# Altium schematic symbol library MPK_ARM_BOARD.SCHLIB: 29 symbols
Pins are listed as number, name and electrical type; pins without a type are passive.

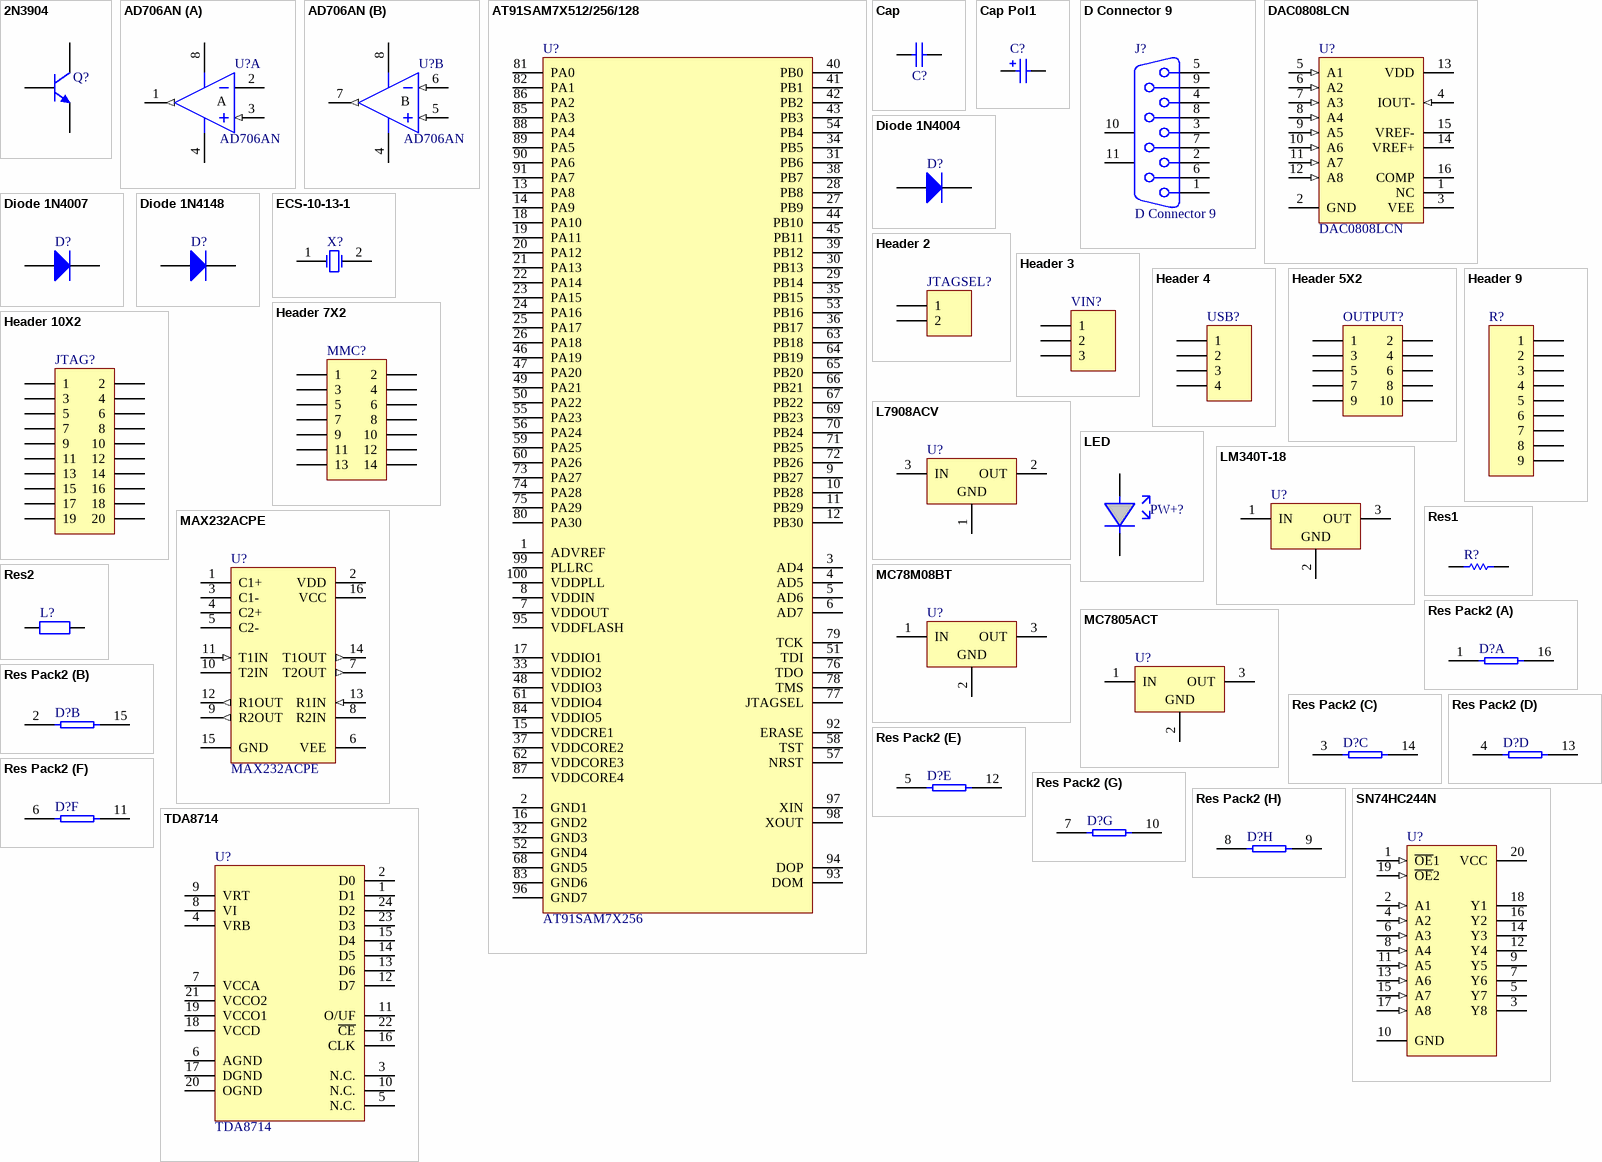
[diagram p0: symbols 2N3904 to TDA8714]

## 2N3904
designator Q?  (value not drawn)
NPN General Purpose Amplifier; Revision 1: 11-Jul-2000: SIM Model Added.; Revision 2: 17-Jul-2002: Re-released for DXP Platform.; Revision 3: 15-Jan-2003: PCB Footprint 'BCY-W3/D4.7' replaced; Code - JEDEC: TO-92A
footprint BCY-W3/E4 (TO, Flat Index; 3 In-Line, Axial Leads; Body Dia. 4.7mm)
simulation model 2N3904 (NPN)
signal-integrity model 2N3904
pins: 1 E, 2 B, 3 C

## AD706AN
designator U?
Dual Picoampere Input Current Bipolar Operational Amplifier; Revision 1: 10-Jul-2000: SIM Model Added.; Revision 2: 17-Jul-2002: Re-released for DXP Platform.; Code - JEDEC: MO-001-AN
footprint N-8_A (DIP; 8 Leads; Row Spacing 7.62 mm; Pitch 2.54 mm)
simulation model AD706A (SUBCKT)
pins on every part: 4 V- (power), 8 V+ (power)
part A pins: 1 OUT (out), 2 IN-, 3 IN+ (in)
part B pins: 5 IN+ (in), 6 IN- (in), 7 OUT (out)

## AT91SAM7X512/256/128
designator U?, comment AT91SAM7X256
Atmel ARM Core 32 Microcontroller
footprint LQFP100 (QFP; 100 Leads; Body 14 x 14 mm; Pitch 0.5 mm)
pins: 1 ADVREF, 2 GND1, 3 AD4, 4 AD5, 5 AD6, 6 AD7, 7 VDDOUT, 8 VDDIN, 9 PB27, 10 PB28, 11 PB29, 12 PB30, 13 PA8, 14 PA9, 15 VDDCRE1, 16 GND2, 17 VDDIO1, 18 PA10, 19 PA11, 20 PA12, 21 PA13, 22 PA14, 23 PA15, 24 PA16, 25 PA17, 26 PA18, 27 PB9, 28 PB8, 29 PB14, 30 PB13, 31 PB6, 32 GND3, 33 VDDIO2, 34 PB5, 35 PB15, 36 PB17, 37 VDDCORE2, 38 PB7, 39 PB12, 40 PB0, 41 PB1, 42 PB2, 43 PB3, 44 PB10, 45 PB11, 46 PA19, 47 PA20, 48 VDDIO3, 49 PA21, 50 PA22, 51 TDI, 52 GND4, 53 PB16, 54 PB4, 55 PA23, 56 PA24, 57 NRST, 58 TST, 59 PA25, 60 PA26, 61 VDDIO4, 62 VDDCORE3, 63 PB18, 64 PB19, 65 PB20, 66 PB21, 67 PB22, 68 GND5, 69 PB23, 70 PB24, 71 PB25, 72 PB26, 73 PA27, 74 PA28, 75 PA29, 76 TDO, 77 JTAGSEL, 78 TMS, 79 TCK, 80 PA30, 81 PA0, 82 PA1, 83 GND6, 84 VDDIO5, 85 PA3, 86 PA2, 87 VDDCORE4, 88 PA4, 89 PA5, 90 PA6, 91 PA7, 92 ERASE, 93 DOM, 94 DOP, 95 VDDFLASH, 96 GND7, 97 XIN, 98 XOUT, 99 PLLRC, 100 VDDPLL

## Cap
designator C?  (value not drawn)
Capacitor; Value: 100pF
footprint RAD-0.3
simulation model CAP (Capacitor)
signal-integrity model Cap
footprint CAPR5.08-7.8X3.2
footprint CAPR2.54-5.1X3.2
pins: 1, 2

## Cap Pol1
designator C?  (value not drawn)
Polarized Capacitor (Radial); Value: 100pF
footprint RB7.6-15 (Polarized Capacitor (Radial); 2 Leads)
simulation model CAP (Capacitor)
signal-integrity model Cap Pol
footprint CAPPR1.5-4X5
footprint CAPPR1.27-1.96X4.06
footprint CAPPR2-5X6.8
footprint CAPPR5-5X5
footprint CAPPR7.5-16X35
pins: 1, 2

## D Connector 9
designator J?
Receptacle Assembly, 9 Position, Right Angle; Package Information: Latest Revision: O; Positions: 9
footprint DSUB1.385-2H9 (Connector; D Subminiature; 9 Position; Right Angle; Pitch 1.385 mm)
signal-integrity model Connector
pins: 1, 2, 3, 4, 5, 6, 7, 8, 9, 10 MH1, 11 MH2

## DAC0808LCN
designator U?
8-Bit D/A Converter; Package Information: Latest Revision: 2000
footprint N16A (DIP; 16 Leads; Row Spacing 7.62 mm; Pitch 2.54 mm)
pins: 1 NC, 2 GND (power), 3 VEE (power), 4 IOUT- (in), 5 A1 (in), 6 A2 (in), 7 A3 (in), 8 A4 (in), 9 A5 (in), 10 A6 (in), 11 A7 (in), 12 A8 (in), 13 VDD (power), 14 VREF+, 15 VREF-, 16 COMP

## Diode 1N4004
designator D?  (value not drawn)
1 Amp General Purpose Rectifier; Revision 1: 11-Jul-2000: SIM Model Added.; Revision 2: 17-Jul-2002: Re-released for DXP Platform.; Package Information: Latest Revision: Aug-1999; Code - JEDEC: DO-204-AL
footprint DIO10.46-5.3x2.8 (Diode, Axial; Body 5.2 x 2.7 mm (LxDia. max), Lead Dia. 0.86 mm (max))
simulation model 1N4004 (DIODE)
signal-integrity model 1N4004
pins: 1 A, 2 K

## Diode 1N4007
designator D?  (value not drawn)
1 Amp General Purpose Rectifier; Revision 1: 11-Jul-2000: SIM Model Added.; Revision 2: 17-Jul-2002: Re-released for DXP Platform.; Package Information: Latest Revision: Aug-1999; Code - JEDEC: DO-204-AL
footprint DIO10.46-5.3x2.8 (Diode, Axial; Body 5.2 x 2.7 mm (LxDia. max), Lead Dia. 0.86 mm (max))
simulation model 1N4007 (DIODE)
signal-integrity model 1N4007
pins: 1 A, 2 K

## Diode 1N4148
designator D?  (value not drawn)
High Conductance Fast Diode; Revision 1: 11-Jul-2000: SIM Model Added.; Revision 2: 17-Jul-2002: Re-released for DXP Platform.; Code - JEDEC: DO-204-AH
footprint DIO7.1-3.9x1.9 (Diode, Axial; Body 3.8 x 1.9 mm (LxDia. max), Lead Dia. 0.53 mm (max))
simulation model 1N4148 (DIODE)
signal-integrity model 1N4148
pins: 1 A, 2 K

## ECS-10-13-1
designator X?  (value not drawn)
Crystal Oscillator
footprint HC-49U (Quartz Crystal, Thru-Hole; 2 Leads; Body 11.35 x 4.65 x 13.46 mm (LxWxH max))
simulation model XTAL (SUBCKT)
pins: 1 OSC1, 2 OSC2

## Header 2
designator JTAGSEL?  (value not drawn)
Header, 2-Pin
footprint HDR1X2 (Connector; Header; 2 Position)
signal-integrity model Connector
pins: 1, 2

## Header 3
designator VIN?  (value not drawn)
Header, 3-Pin
footprint HDR1X3 (Connector; Header; 3 Position)
signal-integrity model Connector
pins: 1, 2, 3

## Header 4
designator USB?  (value not drawn)
Header, 4-Pin
footprint HDR1X4 (Connector; Header; 4 Position)
signal-integrity model Connector
pins: 1, 2, 3, 4

## Header 5X2
designator OUTPUT?  (value not drawn)
Header, 5-Pin, Dual row
footprint HDR2X5 (Connector; Header; 5x2 Position)
signal-integrity model Connector
pins: 1, 2, 3, 4, 5, 6, 7, 8, 9, 10

## Header 7X2
designator MMC?  (value not drawn)
Header, 7-Pin, Dual row
footprint HDR2X7 (Connector; Header; 7x2 Position)
signal-integrity model Connector
pins: 1, 2, 3, 4, 5, 6, 7, 8, 9, 10, 11, 12, 13, 14

## Header 9
designator R?  (value not drawn)
Header, 9-Pin
footprint HDR1X9 (Connector; Header; 9 Position)
signal-integrity model Connector
pins: 1, 2, 3, 4, 5, 6, 7, 8, 9

## Header 10X2
designator JTAG?  (value not drawn)
Header, 10-Pin, Dual row
footprint HDR2X10 (Connector; Header; 10x2 Position)
signal-integrity model Connector
pins: 1, 2, 3, 4, 5, 6, 7, 8, 9, 10, 11, 12, 13, 14, 15, 16, 17, 18, 19, 20

## L7908ACV
designator U?  (value not drawn)
2% Negative Voltage Regulator; Note: Tab is connected to pin 3 (IN).
footprint TO220V (TO, Thru-Hole, Vertical, Heatsink Mounted; 3 In-Line Leads; Pitch 2.54 mm; Pin sequence 1, 3, 2)
pins: 1 GND (power), 2 OUT (power), 3 IN (power)

## LED
designator PW+?  (value not drawn)
footprint LED
pins: 1, 2

## LM340T-18
designator U?  (value not drawn)
3-Terminal Positive Fixed Voltage Regulator; Note: Heatsink surface connected to pin 2.; Code - JEDEC: TO-262-AA
footprint 221A-04 (TO, Thru-Hole, Vertical, Heatsink Mounted; 3 In-Line Leads; Pitch 2.54 mm)
pins: 1 IN (power), 2 GND (power), 3 OUT (power)

## MAX232ACPE
designator U?
+5V Powered, Multi-Channel RS-232 Driver/Receiver; Package Information: Latest Revision: 1997; Code - JEDEC: MS-001-BB
footprint PE16A (DIP; 16 Leads; Row Spacing 7.62 mm; Pitch 2.54 mm)
pins: 1 C1+, 2 VDD (power), 3 C1-, 4 C2+, 5 C2-, 6 VEE (power), 7 T2OUT (out), 8 R2IN, 9 R2OUT (out), 10 T2IN, 11 T1IN (in), 12 R1OUT (out), 13 R1IN (in), 14 T1OUT (out), 15 GND (power), 16 VCC (power)

## MC78M08BT
designator U?  (value not drawn)
3-Terminal Medium-Current Positive Fixed Voltage Regulator; Note: Pin 2 is electrically connected to TAB; Code - JEDEC: TO-262-AA
footprint 221A-04 (TO, Thru-Hole, Vertical, Heatsink Mounted; 3 In-Line Leads; Pitch 2.54 mm)
pins: 1 IN (power), 2 GND (power), 3 OUT (power)

## MC7805ACT
designator U?  (value not drawn)
3-Terminal Positive Fixed Voltage Regulator; Note: Pin 2 is electrically connected to TAB; Code - JEDEC: TO-262-AA
footprint 221A-04 (TO, Thru-Hole, Vertical, Heatsink Mounted; 3 In-Line Leads; Pitch 2.54 mm)
pins: 1 IN (power), 2 GND (power), 3 OUT (power)

## Res1
designator R?  (value not drawn)
Resistor; Value: 5.00K
footprint AXIAL-0.3 (Resistor; 2 Leads)
simulation model RESISTOR (Resistor)
signal-integrity model Res
pins: 1, 2
1 alternate drawing of the same symbol

## Res2
designator L?  (value not drawn)
Resistor; Value: 1K
footprint AXIAL-0.4 (Resistor; 2 Leads)
simulation model RESISTOR (Resistor)
signal-integrity model Res
pins: 1, 2
1 alternate drawing of the same symbol

## Res Pack2
designator D?  (value not drawn)
Resistor Array - Parts; Code - JEDEC: MO-001-AC; Value: 1K
footprint DIP-16 (DIP; 16 Leads; Row Spacing 7.62 mm; Pitch 2.54 mm)
simulation model RESISTOR (Resistor)
signal-integrity model Res Pack
part A pins: 1, 16
part B pins: 2, 15
part C pins: 3, 14
part D pins: 4, 13
part E pins: 5, 12
part F pins: 6, 11
part G pins: 7, 10
part H pins: 8, 9

## SN74HC244N
designator U?  (value not drawn)
Octal Buffer and Line Driver with 3-State Outputs; Package Information: Latest Revision: Oct-1995
footprint N020 (DIP; 20 Leads; Row Spacing 7.62 mm; Pitch 2.54 mm)
signal-integrity model SN74HC244N
pins: 1 ~{OE}1 (in), 2 A1 (in), 3 Y8 (hiz), 4 A2 (in), 5 Y7 (hiz), 6 A3 (in), 7 Y6 (hiz), 8 A4 (in), 9 Y5 (hiz), 10 GND (power), 11 A5 (in), 12 Y4 (hiz), 13 A6 (in), 14 Y3 (hiz), 15 A7 (in), 16 Y2 (hiz), 17 A8 (in), 18 Y1 (hiz), 19 ~{OE}2 (in), 20 VCC (power)

## TDA8714
designator U?
footprint SOP24
pins: 1 D1, 2 D0, 3 N.C., 4 VRB, 5 N.C., 6 AGND, 7 VCCA, 8 VI, 9 VRT, 10 N.C., 11 O/UF, 12 D7, 13 D6, 14 D5, 15 D4, 16 CLK, 17 DGND, 18 VCCD, 19 VCCO1, 20 OGND, 21 VCCO2, 22 ~{CE}, 23 D3, 24 D2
